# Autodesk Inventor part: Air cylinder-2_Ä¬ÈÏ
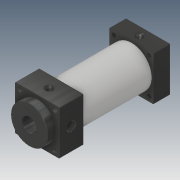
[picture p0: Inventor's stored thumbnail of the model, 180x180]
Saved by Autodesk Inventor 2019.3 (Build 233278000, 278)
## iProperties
Created: 2010-06
Part Number: Air cylinder-2_Ä¬ÈÏ
Material: Ogólny
Document SubType Name: Modeling
Designer: CADENGINEERING4
Density: 1 g/cm^3
Appearance: Domyślna
Author: CADENGINEERING4
Revision Number: ÈÎºÎ
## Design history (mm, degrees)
feature "NONE"
node "Bryła1"
